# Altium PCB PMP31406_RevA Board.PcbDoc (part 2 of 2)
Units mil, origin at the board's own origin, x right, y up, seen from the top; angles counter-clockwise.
Board outline 3986.22 x 3415.35 mil, 2 copper layers (Top Layer, Bottom Layer), stack 62 mil thick; 67 components, 37 nets, 151 pads, 57 vias.
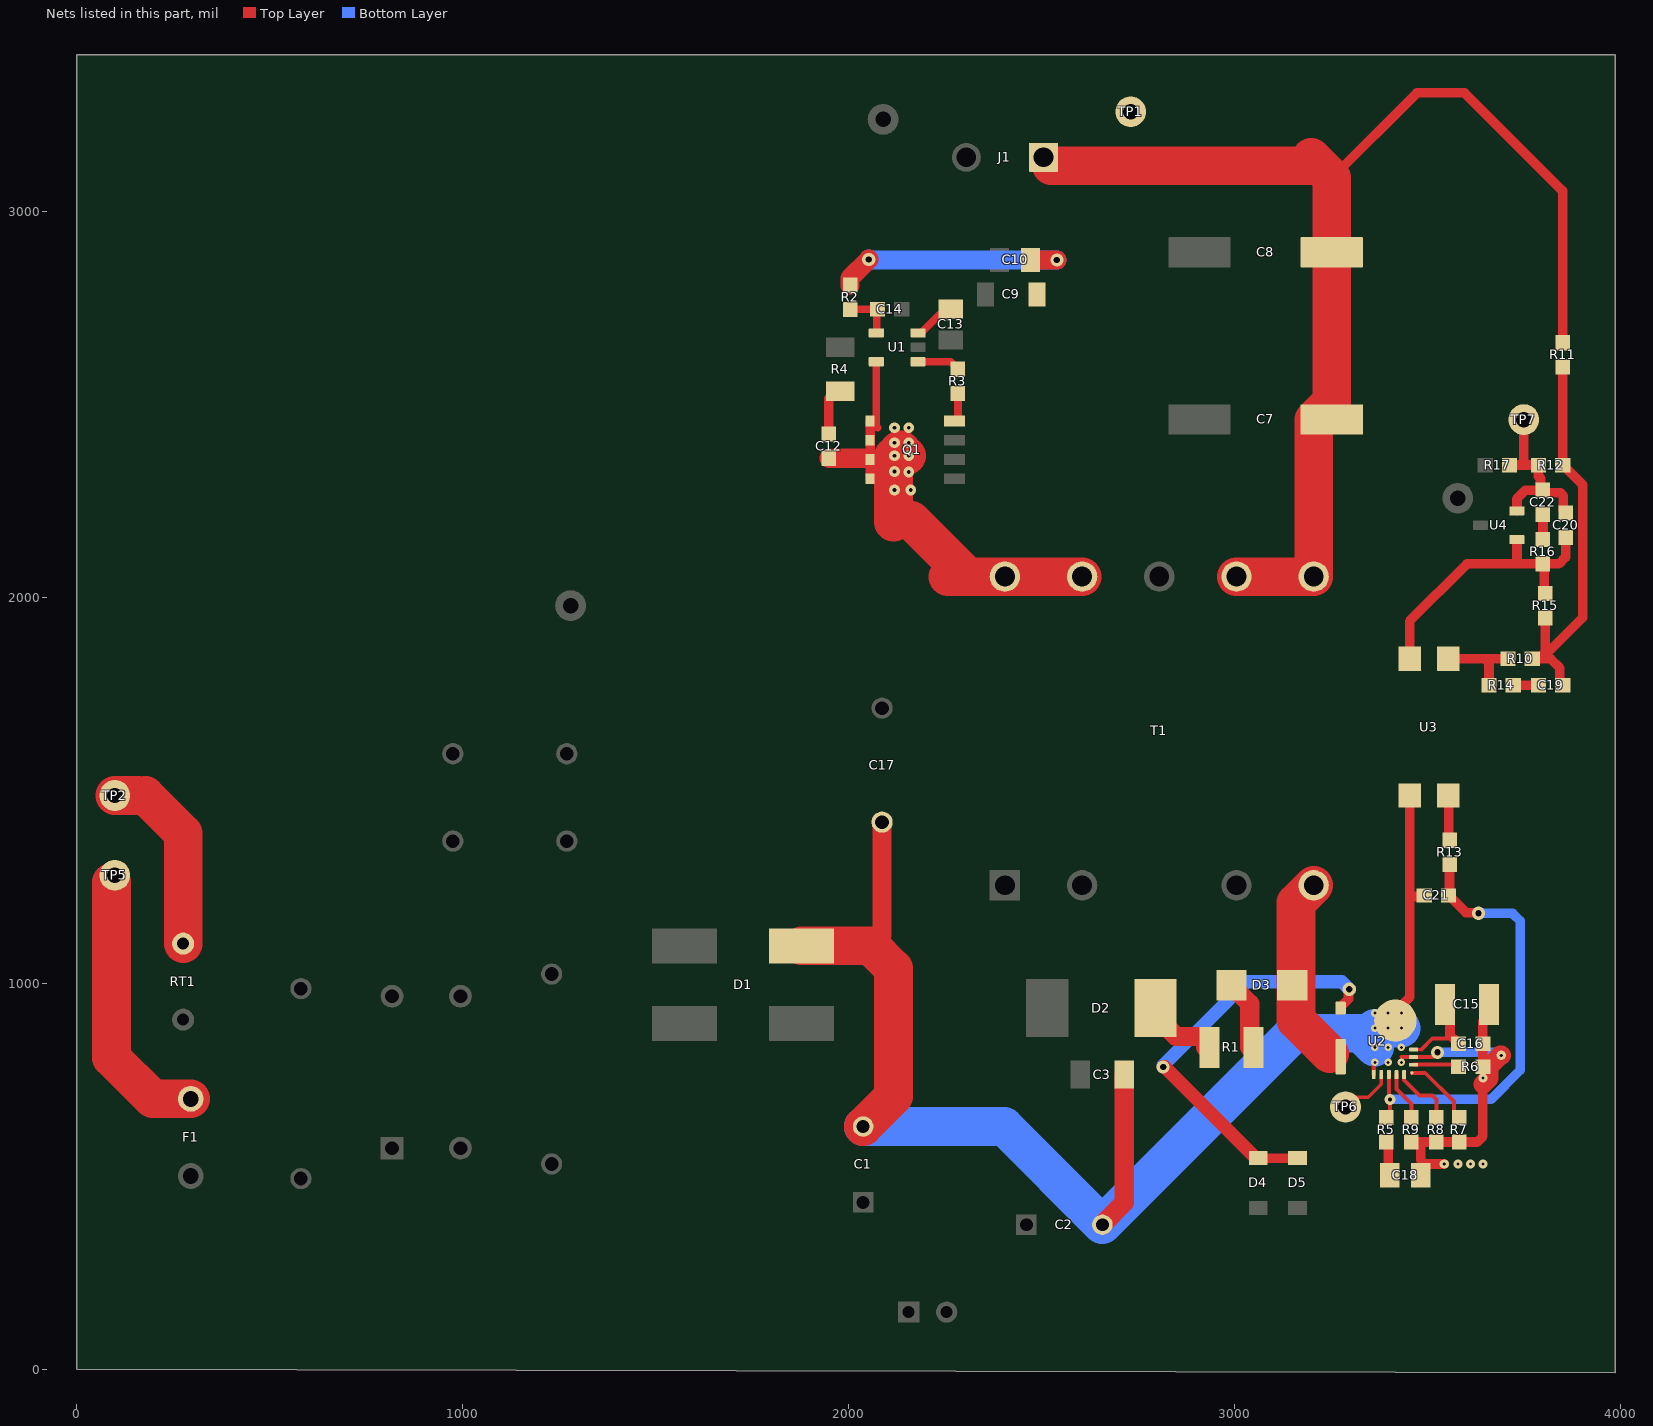
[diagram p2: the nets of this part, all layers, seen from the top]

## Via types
v1: diameter 24, hole 8, Top Layer to Bottom Layer, tented both sides, 25 vias
v2: diameter 19.68, hole 7.87, Top Layer to Bottom Layer, tented both sides, 12 vias
v3: diameter 28, hole 10, Top Layer to Bottom Layer, tented both sides, 11 vias
v4: diameter 34, hole 16, Top Layer to Bottom Layer, tented both sides, 9 vias

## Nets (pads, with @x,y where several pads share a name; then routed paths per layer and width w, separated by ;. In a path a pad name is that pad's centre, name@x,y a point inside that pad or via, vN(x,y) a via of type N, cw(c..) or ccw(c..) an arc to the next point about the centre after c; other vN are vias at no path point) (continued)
NetC12_1: C12.1 Q1.5 Q1.6 Q1.7 Q1.8 T1.9 T1.10 U1.5 | length 1194.2
  Top Layer w20: U1.5@2071.61,2610.24 2071.61,2442.58 2075.1,2439.09
  Top Layer w25: Q1.8@2055.81,2306.89 Q1.7@2055.81,2356.89 2055.81,2360.24 Q1.6@2055.81,2406.89 Q1.5@2055.81,2456.89
  Top Layer w50: C12.1@1948.82,2360.24 Q1.7@2055.81,2360.24
  Top Layer w100: 2116.14,2194.88 2116.14,2365.15 2132.89,2381.89 2134.66,2381.89 v3@2149.94,2366.62 ; 2162.2,2199.88 2303.54,2058.54 ; 2257.48,2053.54 T1.10@2404.88,2053.54 T1.9@2604.88,2053.54
  other v3: 2118.92,2278.17 2160.91,2278.17 2118.92,2325.41 2155.57,2324.56 2118.92,2366.62 2155.57,2366.62 2118.92,2400.28 2155.57,2400.28 2118.92,2439.09 2155.57,2439.01
NetC12_2: C12.2 R4.2 | length 128.8
  Top Layer w25: C12.2@1948.82,2423.23 1948.82,2514.76 1967.52,2533.46 R4.2@1978.35,2533.46
NetC13_1: C13.1 U1.3 | length 110.2
  Top Layer w20: U1.3@2179.88,2685.04 2187.75,2685.04 2234.41,2731.69 2249.53,2731.69 C13.1@2264.53,2746.69
NetC14_1: C14.1 R2.1 U1.4 | length 133.6
  Top Layer w20: R2.1@2003.63,2745.65 2004.15,2746.17 C14.1@2073.09,2746.17 ; U1.4@2071.61,2685.04 2073.09,2686.52 C14.1@2073.09,2746.17 ; C14.1@2073.09,2746.69 C14.1@2073.09,2746.17 ; C14.1@2074.56,2746.69 2074.04,2746.17 C14.1@2073.09,2746.17
NetC15_1: C15.1 C16.1 U2.11 | length 241.7
  Top Layer w8: U2.11@3463.74,828.15 3484.01,828.15
  Top Layer w10: 3484.01,828.15 3512.16,856.3 3556.98,856.3 C16.1@3570.63,842.65
  Top Layer w25: C15.1@3545.04,944.88 3558.13,931.79 3558.13,864.99 3573.29,849.84 3573.29,848.85 3579.49,842.65 C16.1@3580.47,842.65
NetC18_1: C18.1 R5.1 | length 90.3
  Top Layer w25: R5.1@3393.39,588.58 3397.87,584.1 3397.87,506.45 C18.1@3402.35,501.97
NetC19_1: C19.1 R14.2 | length 65
  Top Layer w25: R14.2@3722.2,1771.65 C19.1@3787.16,1771.65
NetC19_2: C19.2 R10.1 R11.1 R12.2 R15.2 | length 1049.7
  Top Layer w25: R15.2@3805.18,1946.85 3805.18,1858.56 3787.16,1840.55 3795.48,1840.55 ; C19.2@3850.16,1771.65 3849.17,1771.65 3842.97,1777.85 3842.97,1816.24 3818.66,1840.55 3795.48,1840.55 ; R11.1@3850.16,2596.46 R12.2@3850.16,2342.52 3851.14,2342.52 3901.78,2291.88 3901.78,1946.85 3795.48,1840.55
NetC20_1: C20.1 R15.1 R16.1 U3.2 U4.1 | length 763.3
  Top Layer w25: U3.2@3453.7,1840.55 3453.7,1938.19 3602.12,2086.61 3731.64,2086.61 ; U4.1@3731.64,2149.11 3731.64,2086.61 ; R15.1@3805.18,2009.84 3802.07,2012.94 3802.07,2083.51 R16.1@3798.97,2086.61 ; C20.1@3858.03,2155.01 3858.03,2104.33 3840.31,2086.61 R16.1@3798.97,2086.61 ; 3731.64,2086.61 R16.1@3798.97,2086.61
NetC20_2: C20.2 C22.1 R12.1 R17.2 TP7.1 U4.2 | length 481.6
  Top Layer w25: R17.2@3712.36,2342.52 3741.89,2342.52 ; U4.2@3731.64,2223.91 3731.64,2255.41 3753.79,2277.56 C22.1@3798.97,2277.56 ; TP7.1@3749.31,2460.24 3749.31,2349.94 cw(c3741.89,2349.94) 3741.89,2342.52 ; C20.2@3858.03,2218 3851.83,2224.2 3851.83,2262.91 3844.37,2270.37 3805.18,2270.37 3798.97,2276.57 C22.1@3798.97,2277.56 ; 3741.89,2342.52 R12.1@3787.16,2342.52 3787.16,2313.98 3792.77,2308.37 3792.77,2283.76 C22.1@3798.97,2277.56
NetC21_1: C21.1 R5.2 R13.1 U2.5 | length 1153.2
  Top Layer w10: R5.2@3393.39,651.57 3402.35,660.53 v3(3402.35,698.82) ; v3@3399.76,698.82 U2.5@3399.76,763.19
  Top Layer w25: C21.1@3554.21,1227.17 3556.98,1227.17 3556.98,1225.38 3599.54,1182.82 3630.51,1182.82 v4(3632.23,1181.1) ; C21.1@3556.98,1239.5 R13.1@3556.98,1307.09
  Bottom Layer w25: v3(3402.35,698.82) 3664.37,698.82 3740.16,774.61 3740.16,1161.42 3720.47,1181.1 v4(3632.23,1181.1)
NetC22_2: C22.2 R16.2 | length 65
  Top Layer w25: R16.2@3798.97,2149.61 C22.2@3798.97,2214.57
NetD2_1: D2.1 R1.2 | length 199.9
  Top Layer w50: D2.1@2795.04,935.43 2795.04,915.43 2848.66,861.81 2924.37,861.81 2924.96,861.22 R1.2@2924.96,833.66
NetD3_1: D3.1 R1.1 | length 180
  Top Layer w50: D3.1@2991.89,994.09 3039.13,946.85 R1.1@3039.13,833.66
NetD3_2: D3.2 T1.5 U2.2 | length 471.9
  Top Layer w100: D3.2@3159.21,984.25 3159.21,903.94 3246.22,816.93 ; D3.2@3159.21,1003.94 3159.21,1207.87 T1.5@3204.88,1253.54
NetD4_1: D4.1 D5.1 U2.1 | length 1081.8
  Top Layer w25: D4.1@3060.79,546.75 D5.1@3163.05,546.75 ; U2.1@3274.76,932.48 U2.1@3276.04,931.2 ; U2.1@3274.76,935.43 3274.76,938.39 3295.28,958.91 3295.28,982.53 v4(3297.01,984.25)
  Top Layer w35: v4(2814.96,782.87) 2818.66,782.87 3054.78,546.75 D4.1@3060.79,546.75
  Bottom Layer w35: v4(2814.96,782.87) 2814.96,787.64 3031.26,1003.94 ; 3039.78,1003.94 3277.32,1003.94 v4(3297.01,984.25)
NetF1_2: F1.2 TP5.1 | length 703.5
  Top Layer w100: TP5.1@90,1261.26 90,807.24 196.85,700.39 F1.2@295.28,700.39
NetQ1_4: Q1.4 R3.1 | length 77.1
  Top Layer w20: Q1.4@2274.42,2456.89 2279.25,2456.89 2283.23,2460.87 R3.1@2283.23,2527.56
NetR3_2: R3.2 U1.1 | length 112.1
  Top Layer w20: U1.1@2179.88,2610.24 2264.53,2610.24 2283.23,2591.54 R3.2@2283.23,2590.55
NetR6_2: R6.2 U2.9 | length 109.3
  Top Layer w10: U2.9@3463.74,788.78 3564.72,788.78 R6.2@3570.63,782.87
NetR7_2: R7.2 U2.8 | length 187.1
  Top Layer w10: U2.8@3459.31,767.62 3493.95,767.62 3568.07,693.5 3568.07,665.28 R7.2@3581.77,651.57
NetR8_2: R8.2 U2.7 | length 165.7
  Top Layer w10: U2.7@3439.13,763.19 3439.21,763.11 3439.21,749.01 3479.56,708.66 3512.87,708.66 3522.71,698.82 R8.2@3522.71,651.57
NetR9_2: R9.2 U2.6 | length 127.6
  Top Layer w10: U2.6@3419.45,763.19 3419.45,725.39 3458.15,686.69 R9.2@3458.15,651.57
NetR10_2: R10.2 R14.1 U3.1 | length 225.3
  Top Layer w25: U3.1@3553.7,1840.55 3648,1840.55 ; R14.1@3659.21,1771.65 3659.21,1829.34 3648,1840.55 ; R10.2@3705.47,1840.55 3648,1840.55
NetR13_2: R13.2 U3.4 | length 117.5
  Top Layer w25: U3.4@3553.7,1486.22 3555.34,1484.58 3555.34,1371.72 R13.2@3556.98,1370.08
NetRT1_1: RT1.1 TP2.1 | length 483.7
  Top Layer w100: TP2.1@98.43,1486.22 157.48,1486.22 ; 177.17,1486.22 275.59,1387.8 RT1.1@275.59,1102.36
NetTP6_1: TP6.1 U2.4 | length 160.5
  Top Layer w10: TP6.1@3274.76,665.28 3313.82,704.33 3346.22,704.33 3380.08,738.19 U2.4@3380.08,763.19
PGND: C1.2 C2.2 C3.2 C15.2 C16.2 C17.2 C18.2 C21.2 D1.4 R6.1 R7.1 R8.1 R9.1 U2.3 U2.10 U2.12 U3.3 | length 4780.7
  Top Layer w10: 3432.24,809.45 3433.23,808.46 U2.10@3463.74,808.46 3513.77,808.46 v4(3526.07,820.76)
  Top Layer w12: U2.3@3360.39,763.19 3360.39,789.65 3363.34,792.61 v2(3363.34,794.69)
  Top Layer w25: U2.12@3422.76,932.12 3453.7,963.06 3453.7,1224.64 ; U3.3@3453.7,1486.22 3453.7,1224.64 ; R9.1@3458.15,588.58 3486.69,588.58 ; C21.2@3491.22,1227.17 3488.69,1224.64 3453.7,1224.64 ; v1(3543.31,531.5) 3492.82,531.5 3482.35,541.97 3482.35,584.24 3486.69,588.58 ; 3643.46,738.19 3643.46,603.23 3628.82,588.58 R7.1@3581.77,588.58 R8.1@3522.71,588.58 3486.69,588.58 ; R6.1@3643.46,782.87 C16.2@3643.46,842.65 3643.46,901.57 3659.21,917.32 C15.2@3659.21,944.88
  Top Layer w50: 2057.56,1096.46 2086.61,1125.51 C17.2@2086.61,1417.32 ; C2.2@2657.48,374.02 2657.48,374.87 2714.33,431.72 C3.2@2714.33,763.19 ; 3643.46,738.19 3658.96,753.68 3658.96,783.6 3688.25,812.89 v1(3690.94,812.89)
  Top Layer w100: D1.4@1877.95,1096.46 2057.56,1096.46 2116.14,1037.88 2116.14,707.31 C1.2@2037.4,628.57
  Bottom Layer w25: v4(3526.07,820.76) 3683.08,820.76 v1(3690.94,812.89)
  Bottom Layer w100: C1.2@2037.4,628.57 2402.93,628.57 C2.2@2657.48,374.02 3153.15,869.68 3327.32,869.68 v2(3363.34,833.66) ; v2(3363.34,883.66) v2(3397.79,883.66) v2(3432.24,883.66)
  other v1: 3578.88,531.5 3611.39,531.5 3643.46,531.5 3643.46,754.33
  other v2: 3397.79,794.69 3432.24,794.69 3397.79,833.66 3432.24,833.66 3363.34,922.64 3397.79,922.64 3432.24,922.64
VOUT: C7.2 C8.2 C9.1 C10.1 J1.1 R2.2 R11.2 T1.6 T1.7 TP1.1 | length 3852.7
  Top Layer w25: 3251.73,3086.61 3472.2,3307.09 3595.63,3307.09 3850.16,3052.56 R11.2@3850.16,2659.45
  Top Layer w50: R2.2@2003.63,2808.64 2003.63,2827.04 v4(2052.03,2875.44) ; C10.1@2471.1,2874.02 v4(2539.37,2874.02)
  Top Layer w100: J1.1@2524.84,3118.1 3218.54,3118.1 ; T1.7@3004.88,2053.54 T1.6@3204.88,2053.54 3204.88,2460.24 3251.73,2507.09 C8.2@3251.73,2893.7 3251.73,3086.61 3198.58,3139.76
  Bottom Layer w50: v4(2052.03,2875.44) 2053.46,2874.02 v4(2539.37,2874.02)
pads on no net: T1.1 T1.4 T1.8

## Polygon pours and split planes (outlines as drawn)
NetC12_1 on Bottom Layer "BOTTOM_LAYER_NETC12_1_P000" (solid, remove dead copper, pour order 0): 1919.29,2266.83 ccw(c1938.98,2266.83) 1938.98,2247.15 2266.4,2247.15 ccw(c2266.4,2279.13) 2298.38,2279.13 2298.38,2469.11 ccw(c2269.46,2469.11) 2269.46,2498.03 1935.04,2498.03 ccw(c1935.04,2482.28) 1919.29,2482.28
GND on Bottom Layer "BOTTOM_LAYER_GND_P009" (solid, remove dead copper, pour order 9): 1712.6,3316.93 cw(c1775.69,3316.93) 1775.69,3380.02 3873.91,3380.02 cw(c3873.91,3336.61) 3917.32,3336.61 3917.32,2185.04 cw(c3887.8,2185.04) 3887.8,2155.51 1761.81,2155.51 cw(c1761.81,2204.72) 1712.6,2204.72
PGND on Bottom Layer "BOTTOM_LAYER_PGND_P007" (solid, remove dead copper, pour order 7): 1968.5,718.5 1968.5,590.55 ccw(c1998.03,590.55) 1998.03,561.02 2478.74,561.02 cw(c2478.74,461.02) 2578.74,461.02 2578.74,403.54 ccw(c2657.48,403.54) 2657.48,324.8 2764.17,324.8 ccw(c2764.17,424.8) 2864.17,424.8 2864.17,598.43 cw(c2964.17,598.43) 2964.17,698.43 3011.81,698.43 ccw(c3011.81,757.49) 3070.87,757.49 3070.87,758.38 cw(c3109.73,758.38) 3109.73,797.24 3415.35,797.24 ccw(c3415.35,851.53) 3469.64,851.53 3469.64,883.66 ccw(c3446.26,883.66) 3446.26,907.05 3143.81,907.05 ccw(c3143.81,863.63) 3100.39,863.63 2952.76,721.76 1978.35,728.35
PGND on Bottom Layer "BOTTOM_LAYER_PGND_P001" (solid, remove dead copper, pour order 1): 3799.21,1253.54 cw(c3799.21,1204.33) 3848.43,1204.33 3848.43,98.43 cw(c3769.69,98.43) 3769.69,19.68 3267.72,19.68 cw(c3267.72,49.21) 3238.19,49.21 3238.19,863.63 cw(c3299.59,863.63) 3299.59,925.03 3330.3,925.03 ccw(c3330.3,958.07) 3363.34,958.07 3363.34,1214.54 cw(c3402.35,1214.54) 3402.35,1253.54
NetC12_1 on Top Layer "TOP_LAYER_NETC12_1_P002" (solid, remove dead copper, pour order 2): 2213.58,2439.01 2213.58,2466.26 ccw(c2197.56,2466.26) 2197.56,2482.28 2013.58,2482.28 ccw(c2013.58,2456.89) 1988.19,2456.89 1988.19,2037.4 ccw(c2017.72,2037.4) 2017.72,2007.87 2269.35,2007.87 ccw(c2269.35,2012.94) 2274.42,2012.94 2274.42,2036.6 ccw(c2257.48,2036.6) 2257.48,2053.54 cw(c2257.48,2106.83) 2204.19,2106.83 2204.19,2130.39
GND on Top Layer "TOP_LAYER_GND_P008" (solid, remove dead copper, pour order 8): 1712.6,3380.02 3897.64,3380.02 cw(c3897.64,3350.49) 3927.17,3350.49 3927.17,1841.62 cw(c3901.78,1841.62) 3901.78,1816.24 3617.41,1816.24 cw(c3617.41,1899.61) 3534.04,1899.61 3534.04,2159.69 ccw(c3438.32,2159.69) 3438.32,2255.41 1750.11,2255.41 cw(c1750.11,2292.92) 1712.6,2292.92 1712.6,3280.29 cw(c1812.6,3280.29) 1812.6,3380.29 1826.96,3380.29
PGND on Top Layer "TOP_LAYER_PGND_P006" (solid, remove dead copper, pour order 6): 3346.22,1487.2 cw(c3374.77,1487.2) 3374.77,1515.75 3887.8,1515.75 cw(c3887.8,1486.22) 3917.32,1486.22 3917.32,98.43 cw(c3848.43,98.43) 3848.43,29.53 3326.77,29.53 cw(c3326.77,78.74) 3277.56,78.74 3277.56,690.73 cw(c3312.23,690.73) 3312.23,725.39 ccw(c3312.23,759.39) 3346.22,759.39 3346.22,774.02
NetC2_1 on Top Layer "TOP_LAYER_NETC2_1_P005" (solid, remove dead copper, pour order 5): 2381.89,1151.57 ccw(c2381.89,1112.2) 2342.52,1112.2 2342.52,314.96 ccw(c2362.2,314.96) 2362.2,295.28 2516.31,295.28 ccw(c2516.31,347.87) 2568.9,347.87 2568.9,1131.89 ccw(c2549.21,1131.89) 2549.21,1151.57 2514.05,1151.57
VOUT on Top Layer "TOP_LAYER_VOUT_P004" (solid, remove dead copper, pour order 4): 2471.1,2784.45 ccw(c2499.65,2784.45) 2499.65,2755.91 2712.95,2755.91 ccw(c2712.95,2807.09) 2764.13,2807.09 2764.13,3098.78 cw(c2805.12,3098.78) 2805.12,3139.76 3120.08,3139.76 ccw(c3120.08,3159.45) 3139.76,3159.45 3139.76,3356.41 ccw(c3116.15,3356.41) 3116.15,3380.02 2494.2,3380.02 ccw(c2494.2,3336.61) 2450.79,3336.61 2450.79,2810 ccw(c2504.88,2810) 2504.88,2755.91
VOUT on Top Layer "TOP_LAYER_VOUT_P003" (solid, remove dead copper, pour order 3): 2962.6,2012.94 2962.6,2247.83 cw(c3021.65,2247.83) 3021.65,2306.89 ccw(c3021.65,2375.79) 3090.55,2375.79 3090.55,3336.61 cw(c3139.76,3336.61) 3139.76,3385.83 3464.57,3385.83 cw(c3464.57,3356.3) 3494.09,3356.3 3494.09,2091.68 cw(c3415.35,2091.68) 3415.35,2012.94

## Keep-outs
Keep-Out Layer:
  text ".Layer_Name" at 577,-858.49 h60

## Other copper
Top Layer:
  text ".Layer_Name" at 577,-858.49 h60
Bottom Layer:
  text ".Layer_Name" at 577,-858.49 h60

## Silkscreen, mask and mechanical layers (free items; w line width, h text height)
Top Overlay:
  text "PMP31362_RevA" at 153.64,121.09 h100
  text ".Layer_Name" at 577,-858.49 h60
Bottom Overlay:
  text ".Layer_Name" at 577,-858.49 h60
Top Paste:
  text ".Layer_Name" at 577,-858.49 h60
Bottom Paste:
  text ".Layer_Name" at 577,-858.49 h60
Top Solder:
  text ".Layer_Name" at 577,-858.49 h60
  text ".Layer_Name" at 577,-858.49 h60
Bottom Solder:
  text ".Layer_Name" at 577,-858.49 h60
Drill Guide:
  text ".Layer_Name" at 577,-858.49 h60
M1 Board Outline:
  the board outline again, w10
  text ".Layer_Name" at 577,-858.49 h60
M2 Board Dimensions:
  rectangle: 125,-400 500,-275
  rectangle: 0,-275 125,-150
  lines w7: 0,-275 1000,-275 ; 125,-400 125,-150 ; 250,-400 250,-150 ; 500,-400 500,-150 ; 750,-400 750,-150 ; 0,-400 0,-150 1000,-150 1000,-400 0,-400
  text ".Layer_Name" at 577,-858.49 h60
M3 3D STEP Top:
  text ".Layer_Name" at 577,-858.49 h60
M4 3D STEP Bottom:
  text ".Layer_Name" at 577,-858.49 h60
M5 Assembly Top:
  lines w10: -292,-930.17 6308,-930.17 ; -292,-726.83 6310,-726.83 ; -292,-523.5 -292,-1133.5 3713,-1133.5 6310,-1133.5 6310,-523.5 -291.5,-523.5 -291.5,-1133.5 1284,-1133.5 ; 2173,-1133.5 2173,-523.5 ; 3440,-726.83 3440,-523.5 ; 4280,-726.83 4280,-523.5 ; 4902,-1140 4902,-937.17
  text "COMPONENTS MARKED 'DNP' SHOULD NOT BE POPULATED." at 1153.5,-318.5 h60
  text "ASSEMBLY VARIANT:" at 1153,-434 h60
  text ".VariantName" at 2189,-434 h60
  text "PCB VIEWED FROM TOP SIDE" at -228.5,-655.67 h60
  text "BOARD #:" at 2248,-655.67 h60
  text ".PRJ_Number" at 2793.5,-655.67 h60
  text "REV:" at 3638,-655.67 h60
  text ".PCB_Rev" at 3929.5,-655.67 h60
  text "SVN REV:" at 4476,-655.67 h60
  text ".VersionControl_RevNumber" at 4982,-655.67 h60
  text "PLOT NAME =" at -228.5,-1064.34 h60
  text ".plot_File_Name" at 577,-1064.34 h60
  text "GENERATED    :" at 2250,-1064.34 h60
  text ".Print_Date" at 3119.5,-1064.34 h60
  text ".Print_Time" at 3848.5,-1064.34 h60
  text "TEXAS INSTRUMENTS" at 5113,-1064.34 h60
M6 Assembly Bottom:
  lines w10: -292.5,-727.33 6309.5,-727.33 ; -290.5,-930.67 6309.5,-930.67 ; 1115.5,-1140.5 1115.5,-937.67 ; 1737.5,-727.33 1737.5,-524 ; 2577.5,-727.33 2577.5,-524 ; 3844.5,-1134 3844.5,-524 ; 4733.5,-1134 6309,-1134 6309,-524 -292.5,-524 -292.5,-1134 2304.5,-1134 6309.5,-1134 6309.5,-524
  text "COMPONENTS MARKED 'DNP' SHOULD NOT BE POPULATED." at 6102,-318 h60
  text ".VariantName" at 5058,-434 h60
  text "ASSEMBLY VARIANT:" at 6097,-434 h60
  text ".VersionControl_RevNumber" at 1035.5,-656.17 h60
  text "SVN REV:" at 1541.5,-656.17 h60
  text ".PCB_Rev" at 2088,-656.17 h60
  text "REV:" at 2379.5,-656.17 h60
  text ".PRJ_Number" at 3224,-656.17 h60
  text "BOARD #:" at 3769.5,-656.17 h60
  text "PCB VIEWED FROM BOTTOM SIDE" at 6246,-656.17 h60
  text "TEXAS INSTRUMENTS" at 904.5,-1064.84 h60
  text ".Print_Time" at 2169,-1064.84 h60
  text ".Print_Date" at 2898,-1064.84 h60
  text "GENERATED    :" at 3767.5,-1064.84 h60
  text ".plot_File_Name" at 5440.5,-1064.84 h60
  text "PLOT NAME =" at 6246,-1064.84 h60
M9 Title Sheet:
  drawing of 63 lines, arcs and shapes, not listed
  text "1" at 1389.5,18376 h70
  text "2" at 5384.5,18376 h70
  text "3" at 9379.5,18376 h70
  text "4" at 13380.51,18376 h70
  text "5" at 17378.84,18376 h70
  text "6" at 21377.18,18376 h70
  text "7" at 25378.84,18376 h70
  text "8" at 29373.84,18376 h70
  text "A" at -467.5,15978 h70
  text "A" at 31232.5,15978 h70
  text "B" at -467.5,10978 h70
  text "B" at 31232.5,10978 h70
  text "C" at -467.5,5978 h70
  text "C" at 31232.5,5978 h70
  text "D" at -467.5,978 h70
  text "D" at 31232.5,978 h70
  text "PROJECT TITLE:" at 28147.5,268.61 h45
  text ".PRJ_Title" at 28197.5,135.28 h70
  text "DESIGNED FOR:" at 28147.5,-32.39 h45
  text ".PRJ_Customer" at 28197.5,-172.39 h70
  text "FILE NAME:" at 28147.5,-332.39 h45
  text ".PCB_File_Name_No_Path" at 28197.5,-452.39 h70
  text "Texas Instruments (TI) and/or its licensors do not warrant the accuracy or completeness of this specification" at 23178,-614.23 h45
  text "ENGINEER:" at 28147.5,-622.39 h45
  text "LAYOUT BY:" at 29652.5,-622.39 h45
  text "or any information contained therein. TI and/or its licensors do not warrant that this design will meet" at 23133.01,-726.89 h45
  text ".PRJ_Engineer" at 28197.5,-777.38 h70
  text ".PCB_Layout" at 29703,-777.38 h70
  text "the specifications, will be suitable for your application or fit for any particular purpose, or will operate in" at 23133.01,-839.56 h45
  text ".Layer_Name" at 577,-858.49 h60
  text "ALTIUM DESIGNER VERSION:" at 29652.5,-932.39 h45
  text "an implementation. TI and/or its licensors do not warrant that the design is production worthy. You should" at 23133.01,-952.22 h45
  text "completely validate and test your design implementation to confirm the system functionality for your application." at 23178,-1064.89 h45
  text ".print_Scale" at 28197.5,-1065.72 h70
  text ".Application_BuildNumber" at 29703,-1065.72 h70
  text "1" at 1389.5,-1319 h70
  text "2" at 5384.5,-1319 h70
  text "3" at 9379.5,-1319 h70
  text "4" at 13380.51,-1319 h70
  text "5" at 17378.84,-1319 h70
  text "6" at 21377.18,-1319 h70
  text "7" at 25378.84,-1319 h70
  text "8" at 29373.84,-1319 h70
M10 Fab Notes:
  drawing of 189 lines, arcs and shapes, not listed
  text "DESIGN INFORMATION" at 29188.02,6365.17 h60
  text "MIN. TRACK WIDTH:" at 28543.46,6233.05 h60
  text "8" at 29639.7,6233.05 h60
  text "MIL" at 29794.46,6233.05 h60
  text "MIN. CLEARANCE:" at 28543.46,6108.92 h60
  text "7.874" at 29468.5,6108.92 h60
  text "MIL" at 29794.46,6108.92 h60
  text "MIN. VIA PAD SIZE:" at 28543.46,5984.8 h60
  text "24" at 29609.71,5984.8 h60
  text "MIL" at 29794.46,5984.8 h60
  text "0.05mm (2MIL)" at 29238.46,5854.9 h60
  text "MINIMUM ANNULAR RING" at 28214.23,5846.67 h60
  text "EXTERNAL" at 29946.46,5846.67 h60
  text "PER" at 28414.23,5736.55 h60
  text "IPC-D-275 CLASS 2 LEVEL C" at 28634.23,5736.54 h60
  text "MIL, HOLES" at 30122.46,5636.07 h60
  text "+/-" at 29730,5627.48 h60
  text "+/-" at 30584,5627.48 h60
  text "REGISTRATION TOLERANCES:" at 28214.23,5626.42 h60
  text "METAL" at 29414,5626.42 h60
  text "5" at 29990.2,5626.42 h60
  text "3" at 30823.2,5626.42 h60
  text "MIL" at 30939.46,5626.42 h60
  text "HOLE SIZE TOLERANCE (UNLESS OTHERWISE SPECIFIED):" at 28214.23,5528.1 h60
  text "+/-" at 30584,5525.23 h60
  text "3" at 30823.2,5524.17 h60
  text "MIL" at 30939.46,5524.17 h60
  text "MATERIAL:" at 28139.46,5386.52 h60
  text "FR-4 High Tg" at 29125.9,5258 h60
  text "X" at 28981.46,5250.01 h60
  text "FR-4" at 28560.46,5245.49 h60
  text "OTHER" at 30048.46,5245.49 h60
  text "62 MIL (1.6mm) +/-10%" at 28880.56,5102.46 h60
  text "X" at 28760.46,5100.01 h60
  text "THICKNESS:" at 28214.23,5094.24 h60
  text "OTHER" at 30165.46,5094.24 h60
  text "TOLERANCE:" at 28214.23,4955.92 h60
  text "X" at 29062.46,4955.92 h60
  text "ANSI IPC-6012 TYPE 3 CLASS 2" at 29240.48,4955.92 h60
  text "OTHER +/-" at 29240.46,4811.73 h60
  text "BOW & TWIST:" at 28214.23,4666.54 h60
  text "X" at 29062.46,4666.54 h60
  text "ANSI IPC-6012 TYPE 3 CLASS 2" at 29240.48,4666.54 h60
  text "OTHER +/-" at 29240.46,4519.85 h60
  text "DRILLING:" at 28139.46,4389.23 h60
  text "NC_DRILL FILES" at 29900.46,4284.04 h60
  text "REFERENCE:" at 28214.23,4280.1 h60
  text "X" at 28871.46,4280.01 h60
  text "AS SHOWN" at 29049.46,4280.1 h60
  text "X" at 29772.46,4280.1 h60
  text "OTHER" at 30198.46,4137.85 h60
  text "PTH COPPER THICKNESS:" at 28213.91,4134.32 h60
  text "X" at 29353.14,4134.32 h60
  text "20-30 um" at 29481.14,4134.32 h60
  text "BOARD FINISH:" at 28139.46,3986.73 h60
  text "SILKSCREEN:" at 28294.68,3876.6 h60
  text "X" at 29252.46,3876.6 h60
  text "TOP" at 29369.46,3876.6 h60
  text "X" at 29762.46,3876.6 h60
  text "BOTTOM" at 29880.46,3876.6 h60
  text "SILKSCREEN COLOR:" at 28294.68,3721.41 h60
  text "X" at 29251.46,3721.41 h60
  text "WHITE" at 29369.46,3721.41 h60
  text "OTHER" at 29880.46,3721.41 h60
  text "X" at 29382.46,3577.96 h60
  text "GREEN" at 29500.46,3577.96 h60
  text "OTHER" at 30118.46,3577.96 h60
  text "SOLDER RESIST COLOR:" at 28294.68,3571.1 h60
  text "X" at 29382.46,3423.71 h60
  text "MATTE" at 29500.46,3423.71 h60
  text "SEMI-GLOSS" at 30118,3423.07 h60
  text "IMMERSION GOLD (ENIG)" at 29200.46,3250.94 h60
  text "ENEPIG" at 30538,3243.72 h60
  text "SURFACE FINISH:" at 28139.46,3242.72 h60
  text "X" at 29022.46,3242.72 h60
  text "IMM. TIN/SILVER OR EQUIV" at 28469,3105.4 h60
  text "OTHER" at 29900.46,3101.47 h60
  text "ARRAY/PANEL:" at 28139.46,2946.09 h60
  text "CUT AND TRIM PER M1 BOARD OUTLINE" at 29200.46,2937.87 h60
  text "N.C. ROUTE" at 29200.46,2801.9 h60
  text "X" at 29888.46,2801.9 h60
  text "V. SCORE" at 30066.46,2801.9 h60
  text "CERTIFICATION:" at 28139.46,2672.77 h60
  text "MATERIALS AND WORKMANSHIP FOR ALL PCBS" at 28864.46,2672.77 h60
  text "TO MEET OR EXCEED THE REQUIREMENTS OF:" at 28864.46,2578.71 h60
  text "X" at 28501.97,2450.08 h60
  text "ANSI IPC-A-600F CLASS ->" at 28629.96,2450.08 h60
  text "X" at 30277.97,2450.08 h60
  text "2" at 30387.96,2450.08 h60
  text "1" at 30072.96,2448.58 h60
  text "3" at 30741.96,2448.58 h60
  text "X" at 29313.97,2302.39 h60
  text "RoHS" at 29441.96,2302.39 h60
  text "OTHER" at 30086.36,2302.39 h60
  text "PER ORDER" at 30483.42,2302.39 h60
  text "ALL BOARDS MUST MEET OR EXCEED UL94-V0 REQUIREMENTS." at 28167,2148.57 h60
  text "PCB MUST BEAR THE UL94V-0 UL REGISTERED MATERIAL ID NUMBER" at 28167,2032.5 h60
  text "ADDITIONAL REQUIREMENTS:" at 28139.46,1863.08 h60
  text "MICROSECTION:" at 28214.23,1755.95 h60
  text "YES" at 29119.96,1755.95 h60
  text "REQUIRED" at 29981.46,1611.62 h60
  text "BARE BOARD ELEC. TEST:" at 28214.23,1608.76 h60
  text "NONE" at 29519.96,1608.76 h60
  text "X" at 29863.46,1608.76 h60
  text "PER ORDER" at 30573.46,1608.76 h60
  text "XX MIL VIAS REQUIRE NON-CONDUCTIVE FILL AND PLANARIZE" at 28382.38,1403.82 h59
  text "XX MIL VIAS REQUIRE CONDUCTIVE FILL AND PLANARIZE" at 28390.38,1299.84 h60
  text "OUTER XX MIL TRACES REQUIRE 50 OHM SINGLE-ENDED IMPEDANCE" at 28389.39,1136.46 h58
  text "LAYER 2 & 3 (INNER LAYERS) XX MIL WIDE, XX MIL SPACE / TRACES REQUIRE 100 OHM DIFFERENTIAL IMPEDANCE" at 28381.39,900.74 h60
  text ".Layer_Name" at 577,-858.49 h60
M11 Gerber Information:
  lines w10: -292,-930.17 6308,-930.17 ; -292,-726.83 6310,-726.83 ; -292,-523.5 -292,-1133.5 3713,-1133.5 6310,-1133.5 6310,-523.5 -291.5,-523.5 -291.5,-1133.5 1284,-1133.5 ; 2173,-1133.5 2173,-523.5 ; 3440,-726.83 3440,-523.5 ; 4280,-726.83 4280,-523.5 ; 4902,-1140 4902,-937.17
  text "ALL ARTWORK VIEWED FROM TOP SIDE" at -228.5,-655.67 h60
  text "BOARD #:" at 2248,-655.67 h60
  text ".PRJ_Number" at 2793.5,-655.67 h60
  text "REV:" at 3638,-655.67 h60
  text ".PCB_Rev" at 3929.5,-655.67 h60
  text "SVN REV:" at 4476,-655.67 h60
  text ".VersionControl_RevNumber" at 4982,-655.67 h60
  text "LAYER NAME =" at -228.5,-858.49 h60
  text "PLOT NAME =" at -228.5,-1064.34 h60
  text ".plot_File_Name" at 577,-1064.34 h60
  text "GENERATED    :" at 2250,-1064.34 h60
  text ".Print_Date" at 3119.5,-1064.34 h60
  text ".Print_Time" at 3848.5,-1064.34 h60
  text "TEXAS INSTRUMENTS" at 5113,-1064.34 h60
M12 Stackup:
  drawing of 191 lines, arcs and shapes, not listed
  text "Layer" at 26553.88,18012.74 h60
  text "Name" at 26963.79,18012.74 h60
  text "Material" at 27893.54,18012.74 h60
  text "Thickness" at 28753.3,18012.74 h60
  text "Constant" at 29403.14,18012.74 h60
  text "Board Layer Stack" at 29973,18012.74 h60
  text "Top Overlay" at 26963.79,17892.74 h60
  text "Top Solder" at 26963.79,17772.74 h60
  text "Solder Resist" at 27893.54,17772.74 h60
  text "0.40mil" at 28753.3,17772.74 h60
  text "3.5" at 29403.14,17772.74 h60
  text "1" at 26553.88,17652.74 h60
  text "Top Layer" at 26963.79,17652.74 h60
  text "1.40mil" at 28753.3,17652.74 h60
  text "Dielectric1" at 26963.79,17532.74 h60
  text "FR-4 High Tg" at 27893.54,17532.74 h60
  text "59.20mil" at 28753.3,17532.74 h60
  text "4.8" at 29403.14,17532.74 h60
  text "2" at 26553.88,17412.74 h60
  text "Bottom Layer" at 26963.79,17412.74 h60
  text "1.40mil" at 28753.3,17412.74 h60
  text "Bottom Solder" at 26963.79,17292.74 h60
  text "Solder Resist" at 27893.54,17292.74 h60
  text "0.40mil" at 28753.3,17292.74 h60
  text "3.5" at 29403.14,17292.74 h60
  text "Bottom Overlay" at 26963.79,17172.74 h60
  text ".Layer_Name" at 577,-858.49 h60
M13 Component Bodies Top:
  text ".Layer_Name" at 577,-858.49 h60
M14 Component Bodies Bottom:
  text ".Layer_Name" at 577,-858.49 h60
M15 Courtyards Top:
  text ".Layer_Name" at 577,-858.49 h60
M16 Courtyards Bottom:
  text ".Layer_Name" at 577,-858.49 h60
Drill Drawing:
  circle w10: c5673.54,2788.61 r16.54
  circle w10: c5673.54,2788.61 r27.56
  circle w10: c5673.54,2168.48 r27.56
  lines w10: 5645.98,2044.45 5673.54,2016.89 5701.1,2044.45 5673.54,2072.01 5645.98,2044.45 ; 5645.98,2264.94 5673.54,2278.72 5701.1,2264.94 5687.32,2292.5 5701.1,2320.06 5673.54,2306.28 5645.98,2320.06 5659.76,2292.5 5645.98,2264.94 ; 5645.98,2388.97 5645.98,2402.75 5659.76,2416.53 5645.98,2430.31 5645.98,2444.09 5659.76,2444.09 5673.54,2430.31 5687.32,2444.09 5701.1,2444.09 5701.1,2430.31 5687.32,2416.53 5701.1,2402.75 5701.1,2388.97 5687.32,2388.97 5673.54,2402.75 5659.76,2388.97 5645.98,2388.97 ; 5645.98,2512.99 5701.1,2512.99 5701.1,2568.12 5645.98,2568.12 5645.98,2512.99 ; 5645.98,2650.8 5659.76,2650.8 5673.54,2637.02 5687.32,2650.8 5701.1,2650.8 5687.32,2664.58 5701.1,2678.36 5687.32,2678.36 5673.54,2692.14 5659.76,2678.36 5645.98,2678.36 5659.76,2664.58 5645.98,2650.8 ; 5645.98,2940.2 5701.1,2940.2 5673.54,2885.07 5645.98,2940.2 ; 5645.98,3022.88 5659.76,3022.88 5673.54,3009.1 5687.32,3022.88 5701.1,3022.88 5687.32,3036.66 5701.1,3050.44 5687.32,3050.44 5673.54,3064.22 5659.76,3050.44 5645.98,3050.44 5659.76,3036.66 5645.98,3022.88 ; 5645.98,3146.91 5659.76,3146.91 5659.76,3133.13 5687.32,3133.13 5687.32,3146.91 5701.1,3146.91 5701.1,3174.47 5687.32,3174.47 5687.32,3188.25 5659.76,3188.25 5659.76,3174.47 5645.98,3174.47 5645.98,3146.91 ; 5645.98,3257.15 5701.1,3257.15 5701.1,3312.28 5645.98,3312.28 5645.98,3257.15 ; 5657,3028.39 5665.27,3028.39 5673.54,3020.13 5681.81,3028.39 5690.08,3028.39 5681.81,3036.66 5690.08,3044.93 5681.81,3044.93 5673.54,3053.2 5665.27,3044.93 5657,3044.93 5665.27,3036.66 5657,3028.39 ; 5657,3268.18 5690.08,3268.18 5690.08,3301.25 5657,3301.25 5657,3268.18
  lines w12: 5596,1979.68 8822.8,1979.68 ; 5596,3343.97 8822.8,3343.97 ; 5933.36,1855.65 5933.36,3468 ; 6265.06,1855.65 6265.06,3468 ; 6900.91,1855.65 6900.91,3468 ; 7159.71,1855.65 7159.71,3468 ; 7534.46,1855.65 7534.46,3468 ; 8257,1855.65 8257,3468 ; 5596,1855.65 8822.8,1855.65 8822.8,3468 5596,3468 5596,1855.65
  text "Symbol" at 5670.42,3381.18 h72
  text "Quantity" at 5970.57,3381.18 h72
  text "Finished Hole Size" at 6302.26,3381.18 h72
  text "Plated" at 6938.12,3381.18 h72
  text "Hole Type" at 7196.92,3381.18 h72
  text "Drill Layer Pair" at 7571.67,3381.18 h72
  text "Hole Tolerance" at 8294.21,3381.18 h72
  text "12" at 5970.57,3257.15 h60
  text "7.87mil (0.200mm)" at 6302.26,3257.15 h60
  text "PTH" at 6938.12,3257.15 h60
  text "Round" at 7196.92,3257.15 h60
  text "Top Layer - Bottom Layer" at 7571.67,3257.15 h60
  text "25" at 5970.57,3133.13 h60
  text "8.00mil (0.203mm)" at 6302.26,3133.13 h60
  text "PTH" at 6938.12,3133.13 h60
  text "Round" at 7196.92,3133.13 h60
  text "Top Layer - Bottom Layer" at 7571.67,3133.13 h60
  text "11" at 5970.57,3009.1 h60
  text "10.00mil (0.254mm)" at 6302.26,3009.1 h60
  text "PTH" at 6938.12,3009.1 h60
  text "Round" at 7196.92,3009.1 h60
  text "Top Layer - Bottom Layer" at 7571.67,3009.1 h60
  text "9" at 5970.57,2885.07 h60
  text "16.00mil (0.406mm)" at 6302.26,2885.07 h60
  text "PTH" at 6938.12,2885.07 h60
  text "Round" at 7196.92,2885.07 h60
  text "Top Layer - Bottom Layer" at 7571.67,2885.07 h60
  text "2" at 5970.57,2761.05 h60
  text "31.00mil (0.787mm)" at 6302.26,2761.05 h60
  text "PTH" at 6938.12,2761.05 h60
  text "Round" at 7196.92,2761.05 h60
  text "Top Layer - Bottom Layer" at 7571.67,2761.05 h60
  text "2" at 5970.57,2637.02 h60
  text "31.50mil (0.800mm)" at 6302.26,2637.02 h60
  text "PTH" at 6938.12,2637.02 h60
  text "Round" at 7196.92,2637.02 h60
  text "Top Layer - Bottom Layer" at 7571.67,2637.02 h60
  text "4" at 5970.57,2512.99 h60
  text "33.47mil (0.850mm)" at 6302.26,2512.99 h60
  text "PTH" at 6938.12,2512.99 h60
  text "Round" at 7196.92,2512.99 h60
  text "Top Layer - Bottom Layer" at 7571.67,2512.99 h60
  text "14" at 5970.57,2388.97 h60
  text "35.43mil (0.900mm)" at 6302.26,2388.97 h60
  text "PTH" at 6938.12,2388.97 h60
  text "Round" at 7196.92,2388.97 h60
  text "Top Layer - Bottom Layer" at 7571.67,2388.97 h60
  text "8" at 5970.57,2264.94 h60
  text "40.00mil (1.016mm)" at 6302.26,2264.94 h60
  text "PTH" at 6938.12,2264.94 h60
  text "Round" at 7196.92,2264.94 h60
  text "Top Layer - Bottom Layer" at 7571.67,2264.94 h60
  text "2" at 5970.57,2140.91 h60
  text "41.34mil (1.050mm)" at 6302.26,2140.91 h60
  text "PTH" at 6938.12,2140.91 h60
  text "Round" at 7196.92,2140.91 h60
  text "Top Layer - Bottom Layer" at 7571.67,2140.91 h60
  text "11" at 5970.57,2016.89 h60
  text "51.18mil (1.300mm)" at 6302.26,2016.89 h60
  text "PTH" at 6938.12,2016.89 h60
  text "Round" at 7196.92,2016.89 h60
  text "Top Layer - Bottom Layer" at 7571.67,2016.89 h60
  text "100 Total" at 5970.57,1892.86 h60
  text ".Layer_Name" at 577,-858.49 h60
M17 Embedded Cavity:
  text ".Layer_Name" at 577,-858.49 h60
M18 Embedded Assembly:
  text ".Layer_Name" at 577,-858.49 h60
M19 Embedded Keepout:
  text ".Layer_Name" at 587,-848.49 h60

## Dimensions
0,0 to 3986.22,3405.51 on M2 Board Dimensions
0,-400 to 1000,-400 on M2 Board Dimensions
0,0 to -9.84,3405.51 on M2 Board Dimensions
